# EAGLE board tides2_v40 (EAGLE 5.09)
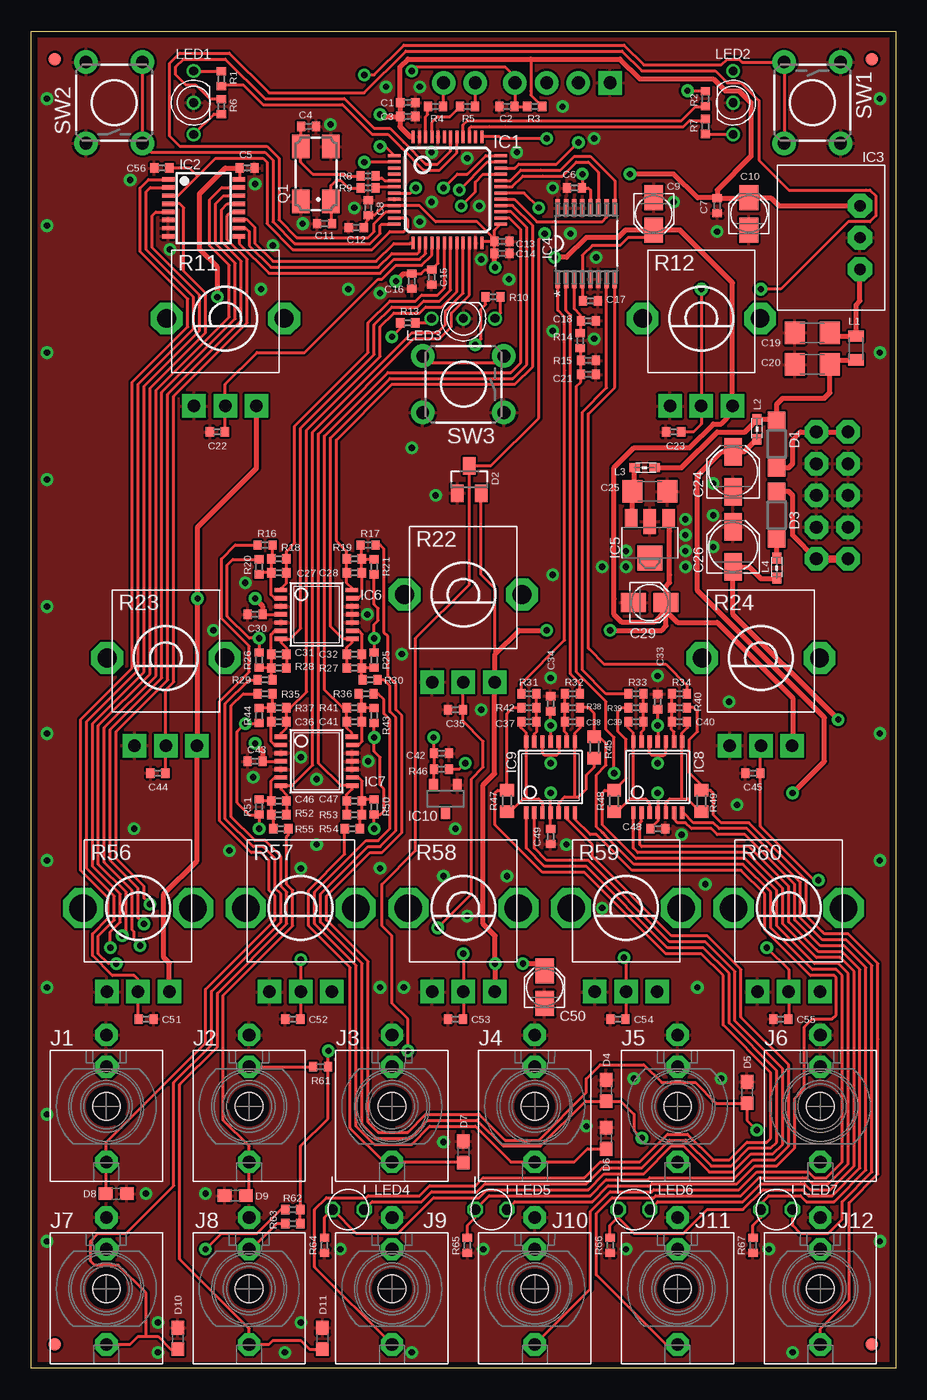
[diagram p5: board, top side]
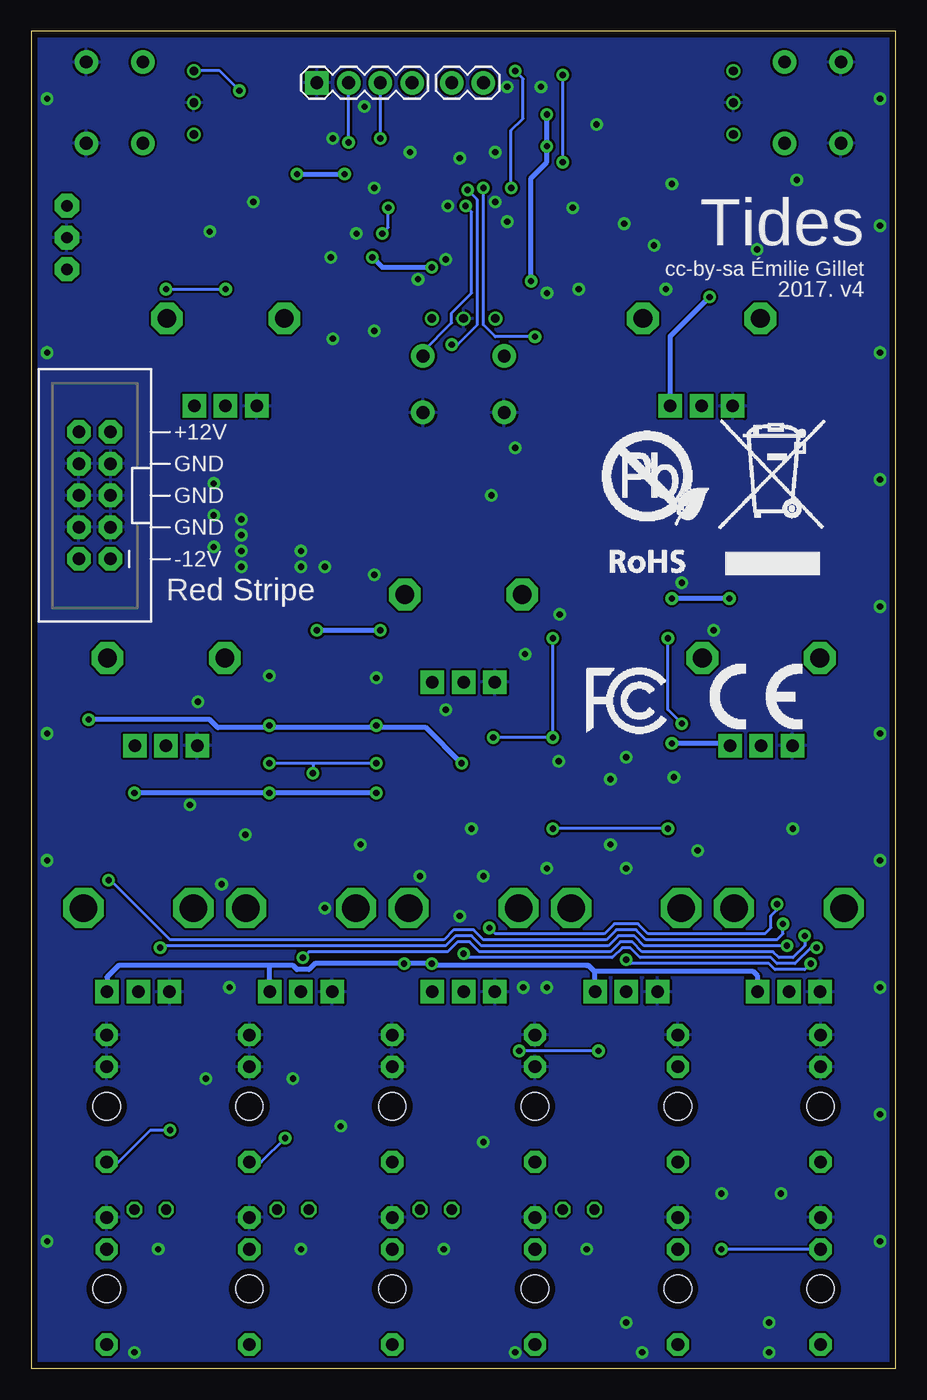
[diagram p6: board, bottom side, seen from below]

Size 69.2 x 107 mm. Coordinates in mm from the lower left corner, seen from the top.
Outline: 69.2,0 0,0 0,107 69.2,107 69.2,0
Copper layers (1*16): Top 0.035mm / dielectric 1.5mm / Bottom 0.035mm
Design rules "PCBCart-Standard": minimum track width 8mil, minimum drill 0.4mm, track to track 7mil, track to pad 7mil, pad to pad 7mil, via to via 7mil, smd to smd 7mil, copper to edge 20mil, drill to drill 8mil, minimum pad ring 8mil, minimum via ring 10mil, stop-mask expansion 3mil, vias tented up to drill 25mil, thermal gap 8mil

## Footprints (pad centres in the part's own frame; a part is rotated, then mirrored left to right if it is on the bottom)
C0402 = smd 0.65 x 0.75: 1 -0.6,0; 2 0.6,0
PANASONIC_A = smd 2 x 1.5: + 1.3,0; - -1.3,0
C1206 = smd 1.6 x 1.8: 1 -1.4,0; 2 1.4,0
PANASONIC_B = smd 2.2 x 1.4: + 1.6,0; - -1.6,0
SOD123 = smd 1.4 x 1.4: A 1.9,0; C -1.9,0
SOT23 = smd 1 x 1.4: 1 -0.95,-1.1; 2 0.95,-1.1; 3 0,1.1
0603 = smd 1.1 x 1: 1 -0.85,0; 2 0.85,0
LQFP48 = smd 0.254 x 1: 1 -2.75,-4.25; 2 -2.25,-4.25; 3 -1.75,-4.25; 4 -1.25,-4.25; 5 -0.75,-4.25; 6 -0.25,-4.25; 7 0.25,-4.25; 8 0.75,-4.25; 9 1.25,-4.25; 10 1.75,-4.25; 11 2.25,-4.25; 12 2.75,-4.25; 25 2.75,4.25; 26 2.25,4.25; 27 1.75,4.25; 28 1.25,4.25; 29 0.75,4.25; 30 0.25,4.25; 31 -0.25,4.25; 32 -0.75,4.25; 33 -1.25,4.25; 34 -1.75,4.25; 35 -2.25,4.25; 36 -2.75,4.25 | smd 1 x 0.254: 13 4.25,-2.75; 14 4.25,-2.25; 15 4.25,-1.75; 16 4.25,-1.25; 17 4.25,-0.75; 18 4.25,-0.25; 19 4.25,0.25; 20 4.25,0.75; 21 4.25,1.25; 22 4.25,1.75; 23 4.25,2.25; 24 4.25,2.75; 37 -4.25,2.75; 38 -4.25,2.25; 39 -4.25,1.75; 40 -4.25,1.25; 41 -4.25,0.75; 42 -4.25,0.25; 43 -4.25,-0.25; 44 -4.25,-0.75; 45 -4.25,-1.25; 46 -4.25,-1.75; 47 -4.25,-2.25; 48 -4.25,-2.75
TSSOP16_065 = smd 0.35 x 1: 1 -1.95,-2.825; 2 -1.3,-2.825; 3 -0.65,-2.825; 4 0,-2.825; 5 0.65,-2.825; 6 1.3,-2.825; 7 1.95,-2.825; 8 2.6,-2.825; 9 2.6,2.825; 10 1.95,2.825; 11 1.3,2.825; 12 0.65,2.825; 13 0,2.825; 14 -0.65,2.825; 15 -1.3,2.825; 16 -1.95,2.825
WE78 = drill 0.9 pad 1.93 octagon: 1 -2.54,0; 2 0,0; 3 2.54,0
SOP65P640X110-16N = smd 1.422 x 0.356: 1 -2.845,2.286; 2 -2.845,1.626; 3 -2.845,0.965; 4 -2.845,0.33; 5 -2.845,-0.33; 6 -2.845,-0.965; 7 -2.845,-1.626; 8 -2.845,-2.286; 9 2.845,-2.286; 10 2.845,-1.626; 11 2.845,-0.965; 12 2.845,-0.33; 13 2.845,0.33; 14 2.845,0.965; 15 2.845,1.626; 16 2.845,2.286
SOT89 = smd 1 x 1.5: 1 -1.499,-1.981; 3 1.499,-1.981 | smd 1 x 2: 2 0,-1.727 | smd 2 x 2: 2@1 0,1.194
TSSOP14_065 = smd 0.35 x 1: 1 -1.95,-2.845; 2 -1.3,-2.845; 3 -0.65,-2.845; 4 0,-2.845; 5 0.65,-2.845; 6 1.3,-2.845; 7 1.95,-2.845; 8 1.95,2.845; 9 1.3,2.845; 10 0.65,2.845; 11 0,2.845; 12 -0.65,2.845; 13 -1.3,2.845; 14 -1.95,2.825
DBZ_R-PDSO-G3 = smd 0.7 x 1: 1 -0.95,-1.1; 2 0.95,-1.1; 3 0,1.1
WQP_PJ_301M6 = drill 1.016 pad 1.778 octagon: P1 0,-5.715; P2 0,-3.175; P3 0,4.445 | hole 2.2: 0,0
FIDUCIAL-1X2 = smd 1 x 1: 1 0,0
2X5-SHROUDED = drill 1.016 pad 1.88 octagon: 1 -1.27,5.08; 2 1.27,5.08; 3 -1.27,2.54; 4 1.27,2.54; 5 -1.27,0; 6 1.27,0; 7 -1.27,-2.54; 8 1.27,-2.54; 9 -1.27,-5.08; 10 1.27,-5.08
1X04 = drill 1.016 pad 1.88 square: 1 0,0 | drill 1.016 pad 1.88 round: 2 2.54,0; 3 5.08,0; 4 7.62,0
1X02 = drill 1.016 pad 1.88 round: 1 0,0; 2 2.54,0
L2012C = smd 0.9 x 1.25: 1 -0.9,0; 2 1,0
0603' = smd 0.85 x 0.7: 1 -0.9,0; 2 0.7,0
LED-BICOLOR-THROUGHHOLE-2.54 = drill 0.7 round: 1 -2.54,0; 2 0,0; 3 2.54,0
LED3MM = drill 0.813 octagon: 1 -1.27,0; 2 1.27,0
CTS406 = smd 1.9 x 1.4: 1 -2.2,-1.2; 2 2.2,-1.2; 3 2.2,1.2; 4 -2.2,1.2
R0402 = smd 0.65 x 0.75: 1 -0.6,0; 2 0.6,0
ALPS_POT_VERTICAL_PS = drill 1 pad 1.88 square: P$1 -2.5,7; P$2 0,7; P$3 2.5,7 | drill 1.5 pad 2.54 octagon: P$4 -4.7,0; P$5 4.7,0
R0603 = smd 1 x 1.1: 1 -0.85,0; 2 0.85,0
ALPS_POT_VERTICAL = drill 1 pad 1.88 square: P$1 -2.5,6.7; P$2 0,6.7; P$3 2.5,6.7 | drill 2.2 pad 3.175 octagon: P$4 -4.4,0; P$5 4.4,0
TACTILE-PTH = drill 1.016 pad 1.88 round: 1 -3.251,2.261; 2 3.251,2.261; 3 -3.251,-2.261; 4 3.251,-2.261

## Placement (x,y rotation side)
C1  1u  [C0402]  30.14,101.28 0 top
C2  100n  [C0402]  38.08,100.97 180 top
C3  100n  [C0402]  30.14,100.17 0 top
C4  20p  [C0402]  22.2,99.38 180 top
C5  100n  [C0402]  17.28,96.04 0 top
C6  100n  [C0402]  43.48,94.46 180 top
C7  100n  [C0402]  54.91,93.03 270 top
C8  100n  [C0402]  26.97,92.87 90 top
C9  10u  [PANASONIC_A]  49.83,92.39 270 top
C10  10u  [PANASONIC_A]  57.45,92.39 90 top
C11  20p  [C0402]  23.47,91.6 0 top
C12  1u  [C0402]  26.02,91.28 180 top
C13  1u  [C0402]  37.68,90.17 0 top
C14  100n  [C0402]  37.68,89.22 0 top
C15  100n  [C0402]  32.05,87.31 270 top
C16  1u  [C0402]  30.46,86.99 270 top
C17  100n  [C0402]  44.75,85.41 0 top
C18  1u  [C0402]  44.59,83.82 0 top
C19  22u  [C1206]  62.53,82.87 180 top
C20  22u  [C1206]  62.53,80.33 180 top
C21  1u  [C0402]  44.59,79.53 0 top
C22  100n  [C0402]  14.9,74.93 180 top
C23  100n  [C0402]  51.41,74.93 180 top
C24  22u  [PANASONIC_B]  56.18,71.75 90 top
C25  22u  [C1206]  49.51,70.17 0 top
C26  22u  [PANASONIC_B]  56.18,65.72 90 top
C27  100p  [C0402]  19.82,63.66 0 top
C28  1.0n  [C0402]  25.86,63.66 180 top
C29  10u  [PANASONIC_A]  49.51,61.28 0 top
C30  100n  [C0402]  17.92,60.33 180 top
C31  100p  [C0402]  19.82,57.15 0 top
C32  1.0n  [C0402]  25.86,57.15 180 top
C33  100n  [C0402]  50.14,53.34 270 top
C34  100n  [C0402]  41.57,53.18 270 top
C35  100n  [C0402]  33.95,52.7 180 top
C36  100p  [C0402]  19.82,51.75 0 top
C37  47p  [C0402]  39.83,51.75 180 top
C38  47p  [C0402]  43.32,51.75 0 top
C39  47p  [C0402]  48.4,51.75 180 top
C40  47p  [C0402]  51.89,51.75 0 top
C41  1.0n  [C0402]  25.86,51.75 180 top
C42  1u  [C0402]  32.84,49.21 0 top
C43  100n  [C0402]  17.92,48.58 180 top
C44  100n  [C0402]  10.14,47.62 180 top
C45  100n  [C0402]  57.76,47.62 180 top
C46  1.0n  [C0402]  19.82,45.4 0 top
C47  1.0n  [C0402]  25.86,45.4 180 top
C48  100n  [C0402]  50.14,43.18 0 top
C49  100n  [C0402]  41.57,42.55 270 top
C50  10u  [PANASONIC_A]  41.1,30.48 90 top
C51  100n  [C0402]  9.19,27.94 0 top
C52  100n  [C0402]  20.93,27.94 180 top
C53  100n  [C0402]  33.95,27.94 180 top
C54  100n  [C0402]  46.97,27.94 180 top
C55  100n  [C0402]  59.99,27.94 180 top
C56  1.0n  [C0402]  10.46,96.04 180 top
D1  1N5819HW  [SOD123]  59.67,73.98 270 top
D2  BAT54S  [SOT23]  35.06,71.12 0 top
D3  1N5819HW  [SOD123]  59.67,68.26 270 top
D4  TVS  [0603]  46.02,22.23 270 top
D5  TVS  [0603]  57.29,22.07 270 top
D6  TVS  [0603]  46.02,18.41 270 top
D7  TVS  [0603]  34.59,17.3 270 top
D8  TVS  [0603]  6.81,13.97 180 top
D9  TVS  [0603]  16.33,13.81 0 top
D10  TVS  [0603]  11.73,2.38 270 top
D11  TVS  [0603]  23.32,2.38 270 top
IC1  STM32F373CCT6  [LQFP48]  33.32,94.3 270 top
IC2  4051PW  [TSSOP16_065]  13.79,93.19 270 top
IC3  R-78E3.3-0.5  [WE78]  66.34,90.49 90 top
IC4  DAC8164ICPW  [SOP65P640X110-16N]  44.43,90.01 90 top
IC5  LD2981ABU33  [SOT89]  49.51,66.04 180 top
IC6  MCP6004  [TSSOP14_065]  22.84,60.33 270 top
IC7  MCP6004  [TSSOP14_065]  22.84,48.58 270 top
IC8  TLV4172  [TSSOP14_065]  50.14,47.31 0 top
IC9  TLV4172  [TSSOP14_065]  41.57,47.31 0 top
IC10  LM4040B10  [DBZ_R-PDSO-G3]  33.16,45.56 180 top
J1  PJ301_THONKICONN6  [WQP_PJ_301M6]  6.01,20.95 180 top
J2  PJ301_THONKICONN6  [WQP_PJ_301M6]  17.44,20.95 180 top
J3  PJ301_THONKICONN6  [WQP_PJ_301M6]  28.87,20.95 180 top
J4  PJ301_THONKICONN6  [WQP_PJ_301M6]  40.3,20.95 180 top
J5  PJ301_THONKICONN6  [WQP_PJ_301M6]  51.73,20.95 180 top
J6  PJ301_THONKICONN6  [WQP_PJ_301M6]  63.16,20.95 180 top
J7  PJ301_THONKICONN6  [WQP_PJ_301M6]  6.01,6.35 180 top
J8  PJ301_THONKICONN6  [WQP_PJ_301M6]  17.44,6.35 180 top
J9  PJ301_THONKICONN6  [WQP_PJ_301M6]  28.87,6.35 180 top
J10  PJ301_THONKICONN6  [WQP_PJ_301M6]  40.3,6.35 180 top
J11  PJ301_THONKICONN6  [WQP_PJ_301M6]  51.73,6.35 180 top
J12  PJ301_THONKICONN6  [WQP_PJ_301M6]  63.16,6.35 180 top
JP1  FIDUCIAL1X2  [FIDUCIAL-1X2]  1.89,104.78 0 top
JP2  FIDUCIAL1X2  [FIDUCIAL-1X2]  67.29,104.77 0 top
JP3  FIDUCIAL1X2  [FIDUCIAL-1X2]  1.89,1.91 0 top
JP4  FIDUCIAL1X2  [FIDUCIAL-1X2]  67.29,1.91 0 top
JP5  M05X2SHD  [2X5-SHROUDED]  64.12,69.85 180 bottom
JP6  [1X04]  46.33,102.87 0 bottom
JP7  [1X02]  33,102.87 180 bottom
L1  33u  [L2012C]  66.02,81.6 90 top
L2  [0603']  58.08,75.25 90 top
L3  [0603']  49.19,72.07 0 top
L4  [0603']  59.67,64.14 90 top
LED1  W115WSURKMGKW  [LED-BICOLOR-THROUGHHOLE-2.54]  13,101.28 90 top
LED2  W115WSURKMGKW  [LED-BICOLOR-THROUGHHOLE-2.54]  56.18,101.28 270 top
LED3  W115WSURKMGKW  [LED-BICOLOR-THROUGHHOLE-2.54]  34.59,84.01 180 top
LED4  3BC-F  [LED3MM]  25.38,12.7 180 top
LED5  3BC-F  [LED3MM]  36.81,12.7 180 top
LED6  3BC-F  [LED3MM]  48.24,12.7 180 top
LED7  3BC-F  [LED3MM]  59.67,12.7 180 top
Q1  8MHz  [CTS406]  22.79,95.57 90 top
R1  2.4k  [R0402]  15.22,103.19 90 top
R2  1.5k  [R0402]  53.95,101.6 90 top
R3  10k  [R0402]  40.3,100.97 180 top
R4  100  [R0402]  32.36,100.97 180 top
R5  100  [R0402]  34.9,100.97 180 top
R6  1.5k  [R0402]  15.22,100.97 270 top
R7  2.4k  [R0402]  53.95,99.38 270 top
R8  100  [R0402]  26.97,95.41 180 top
R9  100  [R0402]  26.97,94.46 180 top
R10  1.5k  [R0402]  36.97,85.73 0 top
R11  10kB  [ALPS_POT_VERTICAL_PS]  15.54,84.01 180 top
R12  10kB  [ALPS_POT_VERTICAL_PS]  53.64,84.01 180 top
R13  2.4k  [R0402]  30.14,83.66 0 top
R14  130k  [R0402]  43.95,82.23 90 top
R15  100k  [R0402]  44.59,80.64 180 top
R16  100k  [R0402]  18.71,65.88 180 top
R17  100k  [R0402]  26.97,65.88 0 top
R18  20k  [R0402]  19.82,64.77 180 top
R19  20k  [R0402]  25.86,64.77 0 top
R20  120k  [R0402]  18.24,64.14 90 top
R21  120k  [R0402]  27.44,64.14 270 top
R22  10kB  [ALPS_POT_VERTICAL_PS]  34.59,61.91 180 top
R23  10kB  [ALPS_POT_VERTICAL_PS]  10.78,56.83 180 top
R24  10kB  [ALPS_POT_VERTICAL_PS]  58.4,56.83 180 top
R25  120k  [R0402]  27.44,56.67 90 top
R26  390k  [R0402]  18.24,56.67 90 top
R27  20k  [R0402]  25.86,56.04 0 top
R28  130k  [R0402]  19.82,56.04 180 top
R29  100k  [R0402]  18.71,55.09 180 top
R30  100k  [R0402]  27.13,55.09 0 top
R31  20k  [R0402]  39.83,53.98 180 top
R32  20k  [R0402]  43.32,53.98 0 top
R33  20k  [R0402]  48.4,53.98 180 top
R34  20k  [R0402]  51.89,53.98 0 top
R35  100k  [R0402]  18.71,53.97 180 top
R36  100k  [R0402]  26.81,53.97 0 top
R37  130k  [R0402]  19.82,52.86 180 top
R38  130k  [R0402]  43.32,52.86 180 top
R39  130k  [R0402]  48.4,52.86 0 top
R40  130k  [R0402]  51.89,52.86 180 top
R41  20k  [R0402]  25.86,52.86 0 top
R42  130k  [R0402]  39.83,52.86 0 top
R43  120k  [R0402]  27.44,52.23 270 top
R44  390k  [R0402]  18.24,52.23 270 top
R45  1.0k  [R0603]  45.06,49.69 270 top
R46  1.5k  [R0402]  32.84,47.94 180 top
R47  1.0k  [R0603]  38.08,45.4 270 top
R48  1.0k  [R0603]  46.65,45.4 270 top
R49  1.0k  [R0603]  53.64,45.4 270 top
R50  140k  [R0402]  27.44,44.93 270 top
R51  120k  [R0402]  18.24,44.93 270 top
R52  20k  [R0402]  19.82,44.29 180 top
R53  33k  [R0402]  25.86,44.29 0 top
R54  100k  [R0402]  25.7,43.18 180 top
R55  100k  [R0402]  19.98,43.18 0 top
R56  10kB  [ALPS_POT_VERTICAL]  8.55,36.83 180 top
R57  10kB  [ALPS_POT_VERTICAL]  21.57,36.83 180 top
R58  10kB  [ALPS_POT_VERTICAL]  34.59,36.83 180 top
R59  10kB  [ALPS_POT_VERTICAL]  47.6,36.83 180 top
R60  10kB  [ALPS_POT_VERTICAL]  60.62,36.83 180 top
R61  10k  [R0402]  23.16,24.13 0 top
R62  10k  [R0402]  20.94,12.7 0 top
R63  10k  [R0402]  20.94,11.59 0 top
R64  1.0k  [R0402]  23.48,9.84 270 top
R65  1.0k  [R0402]  34.9,9.84 270 top
R66  1.0k  [R0402]  46.33,9.84 270 top
R67  1.0k  [R0402]  57.76,9.84 270 top
SW1  [TACTILE-PTH]  62.53,101.28 270 top
SW2  [TACTILE-PTH]  6.65,101.28 90 top
SW3  [TACTILE-PTH]  34.59,78.74 180 top
U$2  [ROHS_BIG]  24.74,62.71 0 bottom
U$4  [CE_MEDIUM]  14.9,51.12 0 bottom
U$5  [FCC_MEDIUM]  24.75,50.8 0 bottom

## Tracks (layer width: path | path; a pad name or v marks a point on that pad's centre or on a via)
+3V3  (via drill 0.5)
  Top 0.254: 30.34,98.55 IC1.48 | v44.11,95.57 44.11,94.49 C6.1 44.59,94.46 44.76,94.28 IC4.12 | IC1.1 28.32,97.79 v27.92,97.79 | 30.43,87.63 C16.1 31.22,87.59 31.54,87.91 C15.1 32.57,88.43 IC1.17 | 39.98,104.78 39.98,102.23 39.98,101.88 R3.1
  Top 0.406: C7.1 54.91,94.3 57.61,97 57.61,101.28 56.65,102.23 55.54,102.23 54.59,103.19 48.72,103.19 47.13,104.78 39.98,104.78 30.14,104.78 29.51,104.14 29.51,101.32 C1.1 C3.1 | C7.1 57.38,93.63 C10.+ 57.48,93.66 59.19,93.66 59.83,93.03 IC3.3 | C3.1 29.51,100.14 29.51,99.38 30.34,98.55 | C7.1 54.87,93.66 53.32,93.66 51.41,95.57 v47.92,95.57 | v27.92,100.33 28.08,100.17 C3.1 | v29.19,87 29.79,87.59 C16.1
  Bottom 0.406: v47.92,95.57 v44.11,95.57 | v27.92,100.33 v27.92,97.79 27.92,96.52 29.19,95.25 v29.19,87
+3V3_A  (via drill 0.5)
  Top 0.254: C30.1 IC6.4 | IC1.25 37.08,91.06 C13.1 | IC1.24 36.19,90.17 C13.1 | C14.1 C13.1 | C13.1 37.08,90.38 35.7,91.76 32.36,91.76 31.09,93.03 29.09,93.03 IC1.9 28.26,93.05 27.48,92.27 C8.1 26.97,91.92 26.81,91.76 26.81,91.47 C12.1 | 44.11,87.18 IC4.4 | D2.2 36.02,63.5 37.13,62.39 37.13,55.4 | C43.1 IC7.4 | IC2.16 16.68,95.2 C5.1 | 44.11,87.18 IC4.4 | C17.1 44.1,85.45 IC4.4 | 44.11,87.18 IC4.4 | 44.11,87.18 44.11,89.06 44.91,89.85 47.13,89.85 47.76,90.49 48.88,90.49 49.83,90.49 C9.+
  Top 0.406: R24.P$1 60.94,49.87 60.94,53.66 54.91,59.69 51.73,59.69 50.81,60.61 | v46.33,59.05 | v41.25,59.05 39.03,59.05 37.13,57.15 37.13,55.4 37.13,54.95 R22.P$1 37.09,47.59 36.17,46.67 36.17,35.56 37.13,34.61 v37.13,32.38 37.13,30.17 R58.P$1 | C50.+ 40.49,32.38 v39.35,32.38 | v17.92,61.59 18.52,60.99 C30.1 | v37.13,88.11 37.08,88.15 C14.1 | R56.P$1 11.05,32.42 10.62,32.86 10.62,37.94 13.28,40.6 R23.P$1 13.32,49.87 v13.32,61.59 13.32,67.31 18.04,72.03 R11.P$1 | v14.9,85.72 14.9,88.11 13.47,89.53 13.47,93.98 15.54,96.04 C5.1 | v17.92,50.01 18.52,49.41 C43.1 | v41.89,88.9 42.84,88.9 44.43,90.49 46.97,90.49 47.57,91.09 C9.+ 51.92,91.09 56.14,86.88 R12.P$1 56.14,76.48 55.22,75.56 54.59,75.56 52.68,73.66 48.24,73.66 46.65,72.07 46.65,61.59 46.65,60.33 47.29,59.69 49.83,59.69 50.81,60.67 C29.+ | IC5.1 51.1,68.02 51.1,66.99 51.1,63.5 51.1,62.87 50.81,62.58 C29.+ | 50.81,60.61 C29.+ | v46.33,59.05 50.46,59.05 50.81,59.4 50.81,60.61
  Bottom 0.406: v41.25,59.05 v46.33,59.05 | 50.14,32.23 48.24,32.23 47.92,31.91 46.97,31.91 46.49,32.38 v39.35,32.38 v37.13,32.38 36.97,32.23 24.75,32.23 | 50.14,32.23 62.21,32.23 63.12,31.31 R60.P$1 | R59.P$1 50.14,30.17 50.14,32.23 | 18.04,61.71 v17.92,61.59 v13.32,61.59 | v17.92,50.01 | v41.89,88.9 41.1,88.11 v37.13,88.11 | v14.9,85.72 18.04,82.59 R11.P$1 | 24.11,31.75 11.41,31.75 11.05,31.39 R56.P$1 | 24.75,32.23 | 24.11,31.75 24.59,32.23 24.75,32.23 | R57.P$1 24.11,30.17 24.11,31.75 | v17.92,50.01 13.95,50.01 13.78,49.83 R23.P$1
ADC_CLOCK
  Top 0.254: IC1.20 34.07,86.16 32.84,84.93 31.57,84.93 31.09,84.45 29.03,84.45 27.92,83.34 27.92,80.96 22.05,75.09 22.05,54.13 20.78,52.86 R37.1 C36.2 20.42,51.24 20,50.81 IC7.1
ADC_FM
  Top 0.254: R52.1 C46.2 20.46,45.44 20.46,45.88 20,46.34 IC7.7 20.89,46.63 22.52,48.26 22.52,74.93 30.46,82.87 32.52,82.87 33.16,83.5 33.16,84.61 34.57,86.02 IC1.21
ADC_SHAPE
  Top 0.254: R27.1 | R27.1 C32.2 25.26,57.66 25.68,58.09 IC6.8 24.95,58.38 23.95,59.37 23.95,74.45 28.71,79.22 38.56,79.22 39.67,80.33 39.67,91.28 38.4,92.55 IC1.27
ADC_SHIFT
  Top 0.254: R19.1 25.22,64.81 | R19.1 C28.2 25.26,62.83 25.66,62.42 IC6.14 | IC1.28 38.54,93.05 40.14,91.44 40.14,80.17 38.71,78.74 28.87,78.74 24.43,74.3 24.43,66.2 25.26,65.37 R19.1
ADC_SLOPE
  Top 0.254: R18.1 20.46,64.81 | R18.1 C27.2 20.42,62.83 20,62.4 IC6.1 | IC1.18 33.07,86.43 32.52,85.88 31.25,85.88 30.78,85.41 28.71,85.41 26.97,83.66 26.97,81.28 21.25,75.56 21.09,75.41 21.09,66.04 20.42,65.37 R18.1
ADC_SMOOTHNESS
  Top 0.254: R41.1 | R41.1 24.9,52.86 23.48,54.29 23.48,74.61 28.55,79.69 38.4,79.69 39.19,80.49 39.19,91.12 38.27,92.05 IC1.26 | R41.1 | R41.1 C41.2 25.26,51.24 25.66,50.83 IC7.14
ADC_TRIG
  Top 0.254: R28.1 C31.2 20.46,57.19 20.46,57.63 20,58.09 IC6.7 20.73,58.38 21.57,59.21 21.57,75.25 27.44,81.12 27.44,83.5 28.87,84.93 30.94,84.93 31.41,85.41 32.68,85.41 33.57,86.29 IC1.19
ADC_V_OCT
  Top 0.254: R53.1 C47.2 25.26,45.91 25.68,46.34 IC7.8 24.79,46.63 23,48.42 23,74.77 30.62,82.39 32.68,82.39 33.63,83.34 33.63,84.45 35.07,85.89 IC1.22
AREF_-10  (via drill 0.5)
  Top 0.254: 18.2,44.29 R51.2 v18.24,43.18 | R20.2 16.14,64.73 15.7,64.29 15.7,60.17 17.44,58.42 v18.24,58.42 | R21.2 | R43.2 | R25.2 | R21.2 27.44,61.12 27.76,60.8 27.76,59.85 27.44,59.53 v27.44,58.42 R25.2 | R43.2 | R43.2 v27.44,50.48 27.44,49.37 27.92,48.9 27.92,46.67 28.24,46.35 28.24,44.61 27.96,44.33 R50.2 | 18.2,44.29 18.24,44.26 | 18.2,44.29 17.44,44.29 16.49,45.24 16.49,50.96 v17.12,51.59 18.2,51.59 R44.2 | v18.24,58.42 | v18.24,58.42 R26.2 | R46.2 32.21,47.91 IC10.2 | R50.2 | v27.44,43.18 R50.2 | v18.24,43.18 | R46.2 | R46.2 C42.1 32.21,49.25 v32.21,50.48
  Bottom 0.254: v27.44,58.42 | v27.44,58.42 v27.44,50.48 v32.21,50.48 | v17.12,51.59 18.24,52.7 v18.24,58.42 | v18.24,43.18 v27.44,43.18 | v27.44,43.18
CLOCK_IN
  Top 0.254: 17.76,53.98 R35.2 16.97,53.98 16.01,53.02 16.01,44.13 17.92,42.23 18.71,42.23 19.98,40.96 19.98,38.58 20.46,38.1 20.46,35.56 14.9,30 14.9,25.72 11.89,22.7 11.89,8.73 17.44,3.17 J8.P3 19.03,1.91 19.35,2.22 21.57,2.22 22.26,1.53 D11.2
DAC_1
  Top 0.254: IC4.1 42.14,84.68 42.68,84.14 42.68,79.85 | R31.2 39.23,54.8 42.68,58.26 42.68,79.85 | 42.68,79.85
DAC_2
  Top 0.254: 42.84,87.13 IC4.2 42.8,84.65 43.16,84.3 43.16,55.56 43.92,54.8 R32.2
DAC_3
  Top 0.254: R33.2 46.02,53.98 44.11,55.88 44.11,76.52 46.06,78.46 IC4.7
DAC_4
  Top 0.254: R34.2 52.49,54.65 50.78,56.36 45.86,56.36 44.67,57.55 44.59,57.63 44.59,76.36 46.72,78.49 IC4.8
DAC_MOSI
  Top 0.254: 45.38,92.87 IC4.11 45.39,95.71 44.59,96.52 43.64,96.52 42.52,95.41 40.94,95.41 39.35,95.41 38.49,94.55 IC1.31
DAC_SCK
  Top 0.254: IC1.29 38.67,93.55 40.46,91.76 45.7,91.76 46.06,92.11 IC4.10
DAC_SS
  Top 0.254: IC1.32 38.35,95.05 39.19,95.89 40.78,95.89 42.37,95.89 43.48,97 44.75,97 46.72,95.03 IC4.9
FM_IN
  Top 0.254: R55.2 20.58,42.67 20.46,42.55 20.46,38.73 20.93,38.26 20.93,35.4 15.38,29.84 15.38,19.84 17.44,17.78 J2.P3 17.44,14.07 D9.2
FREQUENCY_ATT  (via drill 0.5)
  Top 0.254: v6.81,32.38 6.17,32.38 5.38,33.18 5.38,34.61 6.65,35.88 6.65,37.78 4.43,40.01 4.43,51.75 8.55,55.88 8.55,78.74 13,83.19 13,85.72 9.19,89.53 9.19,94.14 9.54,94.49 IC2.2 | C52.1 21.57,27.98 R57.P$2 v21.57,32.7
  Bottom 0.254: v6.81,32.38 7.28,31.91 9.66,31.91 10.14,32.38 21.25,32.38 v21.57,32.7
FREQUENCY_POT
  Top 0.254: C22.1 15.54,74.97 R11.P$2 15.54,78.74 18.08,81.28 21.89,81.28 26.65,86.04 27.76,87.15 28.08,87.15 29.19,88.27 31.25,88.27 32.07,89.08 IC1.16
GND  (via drill 0.5)
  other vias: 42.84,41.91 52.05,42.7 45.06,82.39 41.57,55.24 50.14,55.4 54.59,70.8 54.59,68.26 47.6,64.14 10.14,3.65 21.57,3.65 9.19,13.97 13.95,13.97 33,18.1 55.22,23.18 36.17,9.53 47.6,9.53 59.03,9.53 44.43,19.37 48.24,23.18 26.9,60.33 26.97,48.58 15.86,41.43 21.57,40.01 33,39.37 38.08,39.37 53.32,30.48 45.7,36.83 17.76,47.31 17.12,62.87 21.57,48.9 22.84,47.15 22.84,41.91 54.59,65.72 29.82,30.48 27.92,30.48 33.95,43.18 56.49,45.09 41.73,63.5 45.7,64.14 29.67,57.15 24.75,9.53 1.25,101.6 1.25,91.44 1.25,81.28 1.25,71.12 1.25,60.96 1.25,50.8 1.25,40.64 1.25,30.48 1.25,20.32 1.25,10.16 10.14,1.27 20.3,1.27 30.46,1.27 60.94,1.27 67.92,10.16 67.92,40.64 67.92,50.8 67.92,81.28 67.92,101.6 30.46,73.66 41.73,94.46 11.09,89.53 32.36,69.85 8.24,43.18 53.95,38.73 55.86,53.34 34.9,36.2 36.02,52.7 14.59,59.05 36.02,88.74 27.92,86.04 17.92,94.77 51.41,93.35 23.95,99.54 21.73,91.6 31.09,102.55 32.05,93.34 34.9,96.84 38.87,97.31 45.06,98.42 42.52,100.97 35.86,93.03 27.92,40 38.24,87.15 32.05,97.31 25.38,86.36 41.73,83.03 43.16,90.81 54.91,90.96 25.86,92.87 28.4,102.55 31.09,91.76 18.39,86.36 45.22,88.9 19.35,89.85 52.37,67.94 52.37,66.67 52.37,65.41 52.37,64.14 47.6,65.41 7.92,95.09
  pour Top: 69.2,107 69.2,0 -0.02,0 -0.02,107
  pour Bottom: 69.2,107 69.2,0 -0.02,0 -0.02,107
LED_MODE_G  (via drill 0.5)
  Top 0.254: v35.54,81.92 36.02,82.39 36.02,84.77 36.37,85.12 R10.1 | v34.27,94.3 36.52,96.55 IC1.35
  Bottom 0.254: v34.27,94.3 33.48,93.5 33.48,83.5 35.06,81.92 v35.54,81.92
LED_MODE_R  (via drill 0.5)
  Top 0.254: v28.87,82.55 29.54,83.22 R13.1 | v33,94.46 34.11,95.57 34.9,95.57 36.38,97.05 IC1.36
  Bottom 0.254: v33,94.46 33,83.5 32.05,82.55 v28.87,82.55
LED_RANGE_G
  Top 0.254: R6.1 15.19,101.6 14.27,101.6 13.16,102.71 12.36,102.71 11.57,103.5 11.57,104.14 12.2,104.78 15.54,104.78 18.71,101.6 25.06,101.6 27.44,99.22 28.71,99.22 29.82,98.11 | 33.57,97.88 IC1.42 33.57,97.41 32.52,96.36 31.57,96.36 29.82,98.11 | 29.82,98.11
LED_RANGE_R
  Top 0.254: R1.1 15.34,102.71 16.97,102.71 18.55,101.12 24.9,101.12 27.29,98.74 28.55,98.74 29.67,97.63 | 29.67,97.63 | 29.67,97.63 31.41,95.89 32.68,95.89 34.07,97.27 IC1.41
LED_SHIFT_G
  Top 0.254: R2.1 53.92,100.97 53.32,100.97 53.16,100.97 52.05,99.85 34.9,99.85 34.57,99.52 IC1.40
LED_SHIFT_R
  Top 0.254: R7.1 53.83,99.85 52.68,99.85 52.21,99.38 37.92,99.38 36.65,99.38 35.22,99.38 35.07,99.22 IC1.39
MUX_ADDR_0
  Top 0.254: IC2.11 16.65,91.92 17.28,91.92 17.92,91.28 17.92,90.01 19.35,88.58 27.6,88.58 29.03,90.01 30.3,90.01 30.34,90.05 IC1.13
MUX_ADDR_1
  Top 0.254: 16.66,91.28 IC2.10 17.17,91.24 17.44,90.96 17.44,89.85 19.19,88.11 27.76,88.11 28.87,89.22 30.94,89.22 31.07,89.35 IC1.14
MUX_ADDR_2
  Top 0.254: IC1.15 31.57,89.21 | IC2.9 16.65,90.55 16.65,90.01 19.03,87.63 27.92,87.63 29.03,88.74 31.09,88.74 31.57,89.21 | 31.57,89.21
MUXED_POTS
  Top 0.254: 10.98,93.82 IC2.3 11.74,93.84 13.39,95.49 | IC1.11 30.01,92.05 30.14,91.92 30.14,91.28 29.82,90.96 28.71,90.96 27.29,89.53 20.93,89.53 18.87,91.6 18.87,96.52 18.55,96.84 14.74,96.84 13.39,95.49 | C56.1 12.68,96.04 13.24,95.49 13.39,95.49
N$1
  Top 0.406: C19.1 64.2,82.6 L1.2 66.02,85.09 66.34,85.41 IC3.1
N$2  (via drill 0.5)
  Top 0.254: R62.1 19.98,12.7 18.08,10.79 15.22,10.79 v13.95,9.53
  Bottom 0.254: J7.P2 v13.95,9.53
N$3
  Top 0.254: R63.1 | R63.1 19.66,11.59 17.6,9.53 J8.P2
N$4
  Top 0.254: R16.1 19.31,64.86 R18.2 C27.1 | R20.1 18.36,63.66 C27.1 | C27.1 19.19,63.62 19.19,61.91 19.48,61.62 IC6.2
N$7
  Top 0.254: R8.1 27.73,95.25 28.08,95.25 28.28,95.05 IC1.5
N$8
  Top 0.254: R9.1 27.66,94.55 IC1.6
N$16
  Top 0.254: LED1.3 13.03,103.79 R1.2
N$18
  Top 0.254: LED3.3 31.7,83.66 R13.2
N$20
  Top 0.254: LED3.1 37.57,84.45 R10.2
N$21
  Top 0.254: LED2.3 56.14,98.78 R7.2
N$22
  Top 0.254: LED1.1 14.62,100.36 R6.2
N$23  (via drill 0.5)
  Top 0.254: R2.2 53.92,102.23 v52.53,102.23
  Bottom 0.254: v52.53,102.23 54.11,103.82 LED2.1
N$26
  Top 0.254: J2.P2 R61.1
N$28
  Top 0.254: R17.1 26.46,65.79 R19.2 | R21.1 27.6,64.89 27.6,64.93 27.44,64.77 R19.2 | R19.2 C28.1 26.49,63.62 26.49,61.91 26.2,61.62 IC6.13
N$29
  Top 0.254: R8.2 25.22,95.41 25.06,95.57 22.52,95.57 21.57,96.52 21.57,97.75 Q1.3 21.61,97.79 C4.2
N$30
  Top 0.254: R54.1 26.3,44.13 R53.2 C47.1 26.49,45.44 | 26.49,45.44 26.49,46.99 26.2,47.28 IC7.9 | 26.49,45.44 26.58,45.53 R50.1
N$32
  Top 0.254: R55.1 19.38,44.13 R52.2 C46.1 | R51.1 18.36,45.4 C46.1 | C46.1 19.19,45.44 19.19,46.99 19.48,47.28 IC7.6
N$33
  Top 0.254: R5.1 35.54,101 JP7.2
N$34
  Top 0.254: R29.1 19.22,55.17 R28.2 | R26.1 18.27,56.04 R28.2 | R28.2 C31.1 19.19,57.19 19.19,58.74 19.48,59.02 IC6.6
N$35
  Top 0.254: R9.2 | R9.2 25.38,94.46 24.75,95.09 24.43,95.09 23.99,94.65 Q1.1 23.99,91.68 C11.2
N$37
  Top 0.254: R30.1 26.46,55.16 R27.2 | R27.2 | R27.2 C32.1 26.49,57.19 26.49,58.74 26.2,59.02 IC6.9 | R27.2 26.49,56.07 R25.1
N$38
  Top 0.406: L4.2 D3.A
N$39
  Top 0.254: R37.2 19.31,52.95 R35.1 | R37.2 19.19,52.83 R44.1 | R37.2 C36.1 19.19,51.72 19.19,50.16 19.48,49.88 IC7.2
N$40
  Top 0.406: L1.1 64.3,80.7 C20.1 63.93,78.08 63.48,77.63 60.15,77.63 59.67,77.15 D1.C 59.6,75.95 58.15,75.95 | 58.15,75.95 L2.2 58.15,75.95 | 58.15,75.95 57.13,74.93 54.91,74.93 52.05,72.07 L3.2
N$41
  Top 0.254: R41.2 26.53,52.93 | R43.1 27.41,52.86 R41.2 | R41.2 | R41.2 C41.1 26.49,51.72 26.49,50.16 26.2,49.88 IC7.13 | R36.1 26.46,53.73 R41.2
N$42
  Top 0.406: L3.1 48.29,70.35 C25.1 48.11,68.02 IC5.3
N$45
  Top 0.254: 39.67,45.56 40.62,45.56 40.92,45.26 IC9.3 | R47.2 38.34,44.55 39.35,45.56 39.67,45.56 | 39.67,45.56 39.62,45.61 IC9.14 39.62,50.84 39.19,51.28 39.19,51.72 C37.2
N$49
  Top 0.254: R39.1 47.29,52.86 46.97,52.55 46.97,50.96 47.6,50.32 47.6,47.2 R48.1 45.91,46.25 45.7,46.04 45.7,45.88 45.7,45.72 45.7,43.5 48.4,40.8 57.13,40.8 59.67,38.26 59.67,35.4 62.53,32.54 62.69,32.38 | 62.69,32.38 | 62.69,32.38 64.59,32.38 65.39,31.59 65.39,16.51 65.39,16.35 63.8,14.76 62.53,14.76 62.05,15.24 61.73,15.24 58.24,15.24 56.81,13.81 49.99,13.81 49.83,13.65 49.67,13.65 46.49,13.65 45.22,12.38 45.22,11.75 45.22,11.27 45.22,7.46 50.78,1.91 J11.P3
N$51
  Top 0.254: R4.1 33,101 JP7.1
N$53
  Top 0.254: J9.P3 22.68,8.1 22.68,12.7 23.63,13.65 26.81,13.65 26.97,13.81 31.09,13.81 31.89,14.61 35.54,14.61 36.17,15.24 44.27,15.24 45.54,16.51 48.72,16.51 50.94,18.73 52.53,18.73 54.59,16.67 55.86,16.67 57.29,18.1 58.88,18.1 59.19,18.41 59.19,20 | 59.19,20 59.19,23.65 55.38,27.46 55.38,31.43 53.64,33.18 50.78,33.18 44.27,39.69 40.94,39.69 37.13,43.5 37.13,46.04 37.34,46.25 R47.1 38.08,52.39 38.56,52.86 R42.1 | 59.19,20
N$54
  Top 0.254: R33.1 R39.2 C39.1 49.03,51.72 49.03,51.12 48.84,50.93 IC8.13
N$56
  Top 0.406: D1.A 60.62,72.07 60.94,72.39 60.94,74.3 61.57,74.93 JP5.9 JP5.10
N$58
  Top 0.254: J12.P3 63.16,3.17 65.46,5.48 65.46,13.26 67.77,15.56 67.77,26.35 67.77,32.38 65.39,34.77 63.48,34.77 63.32,34.92 62.05,36.2 62.05,39.05 57.45,43.66 55.22,43.66 54.59,44.29 54.59,46.04 54.38,46.25 R49.1 53.64,46.67 52.68,47.62 52.68,50.32 53.32,50.96 53.32,52.55 53,52.86 R40.1
N$59
  Top 0.254: R34.1 R40.2 C40.1 51.26,51.72 51.26,51.12 51.45,50.93 IC8.9
N$60
  Top 0.254: R38.2 R32.1 | R38.2 | R38.2 C38.1 42.68,51.72 42.68,50.96 42.87,50.77 IC9.9
N$61
  Top 0.254: R42.2 | R42.2 R31.1 | IC9.13 40.27,50.77 40.46,50.96 40.46,51.72 C37.1 R42.2
N$63
  Top 0.254: J10.P3 44.75,6.35 44.75,12.38 44.75,12.54 46.33,14.13 49.67,14.13 49.83,14.29 56.65,14.29 58.08,15.72 61.89,15.72 62.21,15.72 62.69,15.24 63.64,15.24 64.91,16.51 | R38.1 44.59,52.86 45.06,52.39 R45.1 45.48,50.54 46.02,50.01 46.02,48.26 45.22,47.47 45.22,46.51 45.22,43.81 45.22,43.34 45.7,42.86 46.02,42.55 48.24,40.32 56.97,40.32 59.19,38.1 59.19,35.24 62.37,32.07 62.53,31.91 64.43,31.91 64.91,31.43 64.91,31.27 64.91,16.51 | 64.91,16.51
N$64
  Top 0.406: JP5.1 60.94,66.67 60.94,69.85 60.63,70.16 D3.C
  Top 0.61: JP5.1 JP5.2
N$67
  Top 0.254: IC9.2 40.27,41.62 41.25,40.64 44.59,40.64 51.1,34.13 53.95,34.13 56.34,31.75 56.34,27.78 60.15,23.97 60.15,17.94 59.35,17.14 57.61,17.14 56.18,15.72 54.27,15.72 52.21,17.78 51.26,17.78 49.03,15.56 45.86,15.56 44.59,14.29 36.49,14.29 35.86,13.65 32.21,13.65 29.35,10.79 26.02,10.79 LED4.2 23.48,12.06 R64.1
N$68
  Top 0.254: LED4.1 27.29,13.34 31.25,13.34 32.05,14.13 35.7,14.13 36.33,14.76 44.43,14.76 45.7,16.03 48.88,16.03 51.1,18.26 52.37,18.26 54.43,16.19 56.02,16.19 57.45,17.62 59.19,17.62 59.67,18.1 59.67,23.81 55.86,27.62 55.86,31.59 53.8,33.66 50.94,33.66 44.43,40.16 41.1,40.16 39.62,41.64 IC9.1
N$70
  Top 0.254: 43.48,45.72 42.68,45.72 42.22,45.26 IC9.5 | 43.48,45.72 43.79,45.72 44.43,46.35 44.43,47.47 45.06,48.1 R45.2 | 43.48,45.72 43.52,45.77 IC9.8 43.52,50.84 43.95,51.28 43.95,51.72 C38.2
N$71
  Top 0.254: R65.1 34.9,11.43 35.54,12.06 LED5.2 36.65,13.81 44.75,13.81 46.02,15.08 49.35,15.08 49.51,15.24 56.34,15.24 57.76,16.67 59.51,16.67 60.62,17.78 60.62,24.29 56.81,28.1 56.81,31.91 54.11,34.61 51.26,34.61 44.91,40.96 44.91,41.91 42.87,43.94 IC9.6
N$72
  Top 0.254: IC9.7 43.52,43.93 44.75,42.7 45.22,42.7 48.08,39.85 56.81,39.85 58.72,37.94 58.72,35.08 62.37,31.43 64.27,31.43 64.43,31.27 64.43,28.26 64.12,27.94 62.53,27.94 61.89,27.3 61.89,22.38 61.1,21.59 61.1,17.62 59.67,16.19 57.92,16.19 56.49,14.76 49.67,14.76 49.51,14.61 46.18,14.61 44.91,13.34 38.71,13.34 LED5.1 | LED5.1
N$73
  Top 0.254: 48.24,45.56 49.19,45.56 49.49,45.26 IC8.3 | R48.2 46.91,44.55 47.92,45.56 48.24,45.56 | 48.24,45.56 48.2,45.61 IC8.14 48.2,50.84 47.76,51.28 47.76,51.72 C39.2
N$74
  Top 0.254: 48.88,41.75 48.72,41.91 48.72,43.66 48.84,43.78 IC8.2 | R66.1 46.33,11.43 46.97,12.06 | 46.97,12.06 LED6.2 | 48.88,41.75 | 48.88,41.75 57.45,41.75 60.62,38.58 60.62,35.72 62.84,33.5 63,33.34 64.91,33.34 66.34,31.91 66.34,16.03 64.12,13.81 62.21,13.81 61.73,14.29 58.56,14.29 56.97,12.7 54.11,12.7 52.21,10.79 48.24,10.79 46.97,12.06
N$75
  Top 0.254: LED6.1 50.14,13.34 56.97,13.34 58.4,14.76 61.57,14.76 61.89,14.76 62.37,14.29 63.96,14.29 65.86,16.19 65.86,16.35 65.86,31.75 64.75,32.86 62.84,32.86 62.69,33.02 60.15,35.56 60.15,38.42 57.29,41.27 48.56,41.27 48.2,41.64 IC8.1
N$76
  Top 0.254: 52.05,45.56 51.1,45.56 50.79,45.26 IC8.5 | R49.2 53.53,44.55 52.53,45.56 52.05,45.56 | 52.05,45.56 52.09,45.61 IC8.8 52.09,50.84 52.53,51.28 52.53,51.72 C40.2
N$77
  Top 0.254: R67.1 57.76,11.43 58.4,12.06 LED7.2 58.4,13.18 59.03,13.81 61.57,13.81 62.05,13.34 64.27,13.34 66.81,15.88 66.81,32.07 65.07,33.81 63.16,33.81 61.1,35.88 61.1,38.73 57.13,42.7 54.91,42.7 54.43,43.18 52.84,43.18 52.37,43.66 51.73,43.66 51.45,43.94 IC8.6
N$78
  Top 0.254: LED7.1 60.94,11.43 61.57,10.79 63.8,10.79 64.91,11.91 64.91,13.34 67.29,15.72 67.29,32.23 65.23,34.29 63.32,34.29 61.57,36.04 61.57,38.89 57.29,43.18 55.07,43.18 54.59,43.66 53,43.66 52.2,44.46 IC8.7
NORMALIZATION_PROBE  (via drill 0.5)
  Top 0.254: R63.2 R62.2 21.57,12.73 21.57,17.78 23.76,19.97 R61.2 23.76,25.36 v23.79,25.4 | v30.14,25.4 30.14,27.94 28.87,29.21 28.87,34.61 28.08,35.4 28.08,38.73 30.78,41.43 30.78,58.42 35.06,62.71 D2.3 36.8,72.22 40.62,76.04 40.62,90.33 v41.1,90.81 | v40.62,92.87 39.44,94.05 IC1.30
  Bottom 0.254: v23.79,25.4 v30.14,25.4 | v41.1,90.81 40.62,91.28 v40.62,92.87
RESET  (via drill 0.5)
  Top 0.254: v30.78,94.46 30.37,94.05 IC1.7 | C2.1 38.71,101 JP6.4 38.71,103.35 37.92,104.14 30.78,104.14 v30.46,103.82 | C2.1 | C2.1 R3.2
  Bottom 0.254: v30.78,94.46 30.78,99.06 29.82,100.01 29.82,103.19 v30.46,103.82
RX
  Top 0.254: R4.2 31.73,100.93 31.73,100.33 31.57,100.17 IC1.46
SHAPE_ATT  (via drill 0.5)
  Top 0.254: v7.28,34.61 7.6,34.92 7.6,38.1 5.38,40.32 5.38,51.44 9.51,55.56 9.51,78.42 13.95,82.87 13.95,86.04 12.2,87.79 12.2,92.87 11.89,93.19 IC2.4 | v47.45,32.86 47.6,32.7 R59.P$2 47.6,27.98 C54.1
  Bottom 0.254: v7.28,34.61 7.28,33.81 8.24,32.86 9.35,32.86 9.82,33.34 20.3,33.34 21.09,34.13 22.05,34.13 22.84,33.34 33.32,33.34 34.11,34.13 35.06,34.13 35.86,33.34 46.97,33.34 v47.45,32.86 | v47.45,32.86
SHAPE_IN  (via drill 0.5)
  Top 0.254: v48.88,18.41 48.24,19.05 48.24,20.32 47.18,21.38 D4.2 44.37,21.38 40.78,17.78 37.76,17.78 35.7,19.84 31.73,19.84 30.3,18.41 27.6,18.41 26.49,19.53 26.49,32.38 23.16,35.72 23.16,37.94 26.97,41.75 27.92,41.75 29.19,43.02 29.19,52.07 28.71,52.55 28.71,54.61 28.24,55.09 R30.2
  Bottom 0.254: J5.P3 50.78,16.51 v48.88,18.41
SHAPE_POT  (via drill 0.5)
  Top 0.254: C23.1 53,74.93 53.64,75.56 R12.P$2 v53.64,86.36 | IC1.10 28.4,92.55 27.44,91.6 27.44,90.96 26.97,90.49 21.25,90.49 19.82,91.92 19.82,96.84 18.87,97.79 11.89,97.79 11.09,98.58 11.09,104.46 11.89,105.25 15.86,105.25 19.03,102.08 26.65,102.08 29.98,105.41 47.29,105.41 48.88,103.82 54.75,103.82 55.7,102.87 56.81,102.87 58.24,101.44 58.24,96.68 60.62,94.3 66.81,94.3 67.13,94.3 67.61,93.82 67.61,92.23 67.13,91.76 65.39,91.76 59.99,86.36 v58.4,86.36
  Bottom 0.254: v58.4,86.36 v53.64,86.36
SHIFT_ATT  (via drill 0.5)
  Top 0.254: v8.71,33.81 8.24,34.29 8.24,34.92 8.08,35.08 8.08,38.26 5.85,40.48 5.85,51.28 9.98,55.4 9.98,78.26 15.86,84.14 15.86,88.27 14.27,89.85 14.27,93.5 | v58.88,33.66 60.62,31.91 R60.P$2 60.62,27.98 C55.1 | 14.27,93.5 15.25,94.49 IC2.15 | 14.27,93.5
  Bottom 0.254: v58.88,33.66 58.72,33.81 36.02,33.81 35.22,34.61 33.95,34.61 33.16,33.81 23,33.81 22.21,34.61 20.93,34.61 20.14,33.81 v8.71,33.81
SHIFT_IN  (via drill 0.5)
  Top 0.254: 28.24,58.9 28.24,65.56 27.92,65.88 R17.2 | 28.24,58.9 | 28.24,58.9 28.55,58.58 28.55,55.4 29.19,54.77 29.19,52.7 29.67,52.23 29.67,42.86 28.08,41.27 27.13,41.27 23.63,37.78 23.63,35.88 26.97,32.54 26.97,19.68 27.76,18.89 30.14,18.89 31.57,20.32 35.86,20.32 37.92,18.26 40.62,18.26 44.43,22.07 44.43,23.18 45.54,24.29 49.03,24.29 50.46,22.86 53.16,22.86 54.8,21.22 D5.2 57.29,19.84 v58.08,19.05
  Bottom 0.254: J6.P3 62.21,16.51 59.67,19.05 v58.08,19.05
SHIFT_POT  (via drill 0.5)
  Top 0.254: v63,39.05 62.69,39.05 58.36,43.37 C45.1 58.36,49.8 R24.P$2 | v9.03,35.56 8.55,36.04 8.55,38.42 6.33,40.64 6.33,51.12 10.46,55.24 10.46,78.11 16.33,83.98 16.33,88.42 14.74,90.01 | 14.74,90.01 14.74,93.19 15.39,93.84 IC2.14 | 14.74,90.01
  Bottom 0.254: v63,39.05 62.84,39.05 58.08,34.29 36.17,34.29 35.38,35.08 33.79,35.08 33,34.29 23.16,34.29 22.36,35.08 20.78,35.08 19.98,34.29 9.51,34.29 9.03,34.77 v9.03,35.56
SLOPE_ATT
  Top 0.254: C51.1 8.55,27.98 R56.P$2 8.55,31.11 8.24,31.43 6.49,31.43 4.9,33.02 4.9,34.77 6.17,36.04 6.17,37.62 3.95,39.85 3.95,51.91 8.08,56.04 8.08,78.9 12.52,83.34 12.52,85.57 8.71,89.38 8.71,94.46 9.39,95.14 IC2.1
SLOPE_IN
  Top 0.254: R16.2 16.33,65.88 15.22,64.77 15.22,60.01 17.44,57.78 17.44,55.72 15.06,53.34 15.06,43.81 17.6,41.27 18.39,41.27 19.03,40.64 19.03,38.26 19.51,37.78 19.51,35.88 13.95,30.32 13.95,26.04 6.01,18.1 J1.P3 6.01,14.03 D8.2
SLOPE_POT
  Top 0.254: C44.1 10.78,47.66 R23.P$2 10.78,54.29 11.41,54.93 11.41,77.79 17.28,83.66 17.28,88.74 15.7,90.33 15.7,92.23 16,92.54 IC2.12
SMOOTHNESS_ATT  (via drill 0.5)
  Top 0.254: v6.33,33.66 6.33,34.92 7.12,35.72 7.12,37.94 4.9,40.16 4.9,51.59 9.03,55.72 9.03,78.58 13.47,83.03 13.47,85.88 9.66,89.69 9.66,92.23 9.97,92.54 IC2.5 | v34.59,33.18 R58.P$2 34.59,27.98 C53.1
  Bottom 0.254: v6.33,33.66 6.81,33.66 8.08,32.38 9.51,32.38 9.98,32.86 20.46,32.86 21.25,33.66 21.89,33.66 22.68,32.86 34.27,32.86 v34.59,33.18
SMOOTHNESS_IN
  Top 0.254: R36.2 27.76,53.98 28.24,53.5 28.24,52.39 28.71,51.91 28.71,43.18 27.76,42.23 26.81,42.23 22.68,38.1 22.68,35.56 26.02,32.23 26.02,19.37 27.44,17.94 30.46,17.94 31.89,19.37 35.54,19.37 38.4,16.51 J4.P3 43.48,16.51 44.53,17.57 D6.2
SMOOTHNESS_POT  (via drill 0.5)
  Top 0.254: v32.52,35.24 35.22,37.94 35.22,47.15 36.17,48.1 36.17,50.16 34.55,51.79 C35.1 34.55,54.88 R22.P$2 | v9.51,37.15 9.03,37.62 9.03,38.58 6.81,40.8 6.81,50.96 10.93,55.09 10.93,77.95 16.81,83.82 16.81,88.58 15.22,90.17 15.22,92.71 15.7,93.19 IC2.13
  Bottom 0.254: v32.52,35.24 32.05,34.77 23.32,34.77 22.52,35.56 20.62,35.56 19.82,34.77 10.46,34.77 9.98,35.24 9.98,36.2 9.51,36.67 v9.51,37.15
SW_MODE  (via drill 0.5)
  Top 0.254: v34.43,93.03 35.2,93.8 35.54,94.14 35.54,94.93 36.15,95.55 IC1.33 | SW3.4 31.85,80.49 37.45,80.49 37.84,80.88 SW3.3
  Bottom 0.254: v34.43,93.03 34.27,92.87 33.95,92.55 33.95,86.04 35.54,84.45 35.54,83.66 37.84,81.36 SW3.3
SW_RANGE
  Top 0.254: SW2.4 SW2.3 9.63,97.31 18.71,97.31 19.35,96.68 19.35,91.76 21.09,90.01 27.13,90.01 27.92,90.81 27.92,91.44 28.03,91.55 IC1.12
SW_SHIFT  (via drill 0.5)
  Top 0.254: SW1.4 SW1.3 56.89,104.53 56.65,104.78 55.7,104.78 55.22,104.3 49.03,104.3 47.45,105.89 29.82,105.89 27.44,103.5 v26.65,103.5 | v26.65,96.52 26.68,96.55 IC1.2
  Bottom 0.254: SW1.3 60.27,103.94 | v26.65,96.52 v26.65,103.5
SWCLK  (via drill 0.5)
  Top 0.254: IC1.37 36.1,98.58 37.45,98.58 37.6,98.42 v41.25,98.42
  Bottom 0.254: v41.25,98.42 JP6.3
SWDIO  (via drill 0.5)
  Top 0.254: v43.79,98.11 42.05,96.36 39.03,96.36 38.72,96.05 IC1.34
  Bottom 0.254: v43.79,98.11 JP6.2
TRIG_IN
  Top 0.254: 19.98,37.94 19.98,35.72 14.43,30.16 14.43,25.88 11.41,22.86 11.41,14.61 7.6,10.79 5.38,10.79 4.74,10.16 4.74,8.57 5.06,8.26 6.97,8.26 9.19,6.03 9.19,2.54 | 19.98,37.94 | 19.98,37.94 19.51,38.42 19.51,40.8 18.55,41.75 17.76,41.75 15.54,43.97 15.54,53.18 17.44,55.09 R29.2 | 11.35,1.91 D10.2 11.15,1.53 10.14,2.54 9.19,2.54 | J7.P3 7.92,1.91 8.55,2.54 9.19,2.54
TX
  Top 0.254: R5.2 33.51,100.17 32.52,100.17 32.07,99.72 IC1.45
V_OCT_IN
  Top 0.254: 25.1,43.22 R54.2 25.1,41.15 22.21,38.26 22.21,35.4 25.54,32.07 25.54,19.21 28.24,16.51 J3.P3 34.53,16.51 D7.2
VCC  (via drill 0.5)
  Top 0.254: v41.57,46.04 IC9.4 C49.1 | v50.14,46.04 IC8.4 50.14,43.78 C48.1
  Top 0.406: v60.94,46.04 63.48,48.58 63.48,52.07 53.32,62.23 53.32,71.44 55.24,73.36 C24.+ 57.08,73.34 L2.1
  Bottom 0.406: v41.57,46.04 v50.14,46.04 v60.94,46.04
VEE  (via drill 0.5)
  Top 0.254: C34.2 v41.57,51.44 IC9.11 | IC8.11 v50.14,51.44 C33.2 | R46.1 | R46.1 34.27,47.94 v34.75,48.42
  Top 0.406: 64.12,52.39 | v64.59,51.91 64.12,52.39 | 64.12,52.39 56.18,60.33 C26.- | L4.1 59.6,63.17 59.59,63.18 58.4,63.18 57.46,64.12 C26.- | C26.- 56.24,64.19
  Bottom 0.406: 50.14,51.28 v50.14,51.44 | 50.14,51.28 54.27,51.28 54.91,51.91 v64.59,51.91 | v34.75,48.42 37.6,51.28 41.57,51.28 | 41.57,51.28 50.14,51.28 | 41.57,51.28 v41.57,51.44
VREF
  Top 0.254: R14.2 43.99,82.87 C18.1 43.95,83.86 43.95,84.3 43.46,84.78 IC4.3
VREF_BIAS  (via drill 0.5)
  Top 0.254: 41.57,49.05 41.1,49.05 40.92,49.23 IC9.12 | 41.57,49.05 v41.57,48.42 | v46.65,47.62 46.65,50.48 46.02,51.12 46.02,53.34 43.64,55.72 43.64,78.58 43.99,78.93 C21.1 | 41.57,49.05 42.05,49.05 42.22,49.23 IC9.10 | 50.14,49.05 49.67,49.05 49.49,49.23 IC8.12 | v50.14,48.42 50.14,49.05 | 50.14,49.05 50.62,49.05 50.79,49.23 IC8.10 | R14.1 43.99,81.6 R15.2 C21.1 | C21.1
  Bottom 0.254: v41.57,48.42 46.65,48.42 | v50.14,48.42 | v50.14,48.42 | 46.65,48.42 v46.65,47.62 | 46.65,48.42 v50.14,48.42

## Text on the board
bNames: Tides | cc-by-sa Émilie Gillet | 2017. v4 | +12V | GND | GND | GND | -12V | Red Stripe
tStop: cc-by-sa | Émilie Gillet | 2017. v4 | Tides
